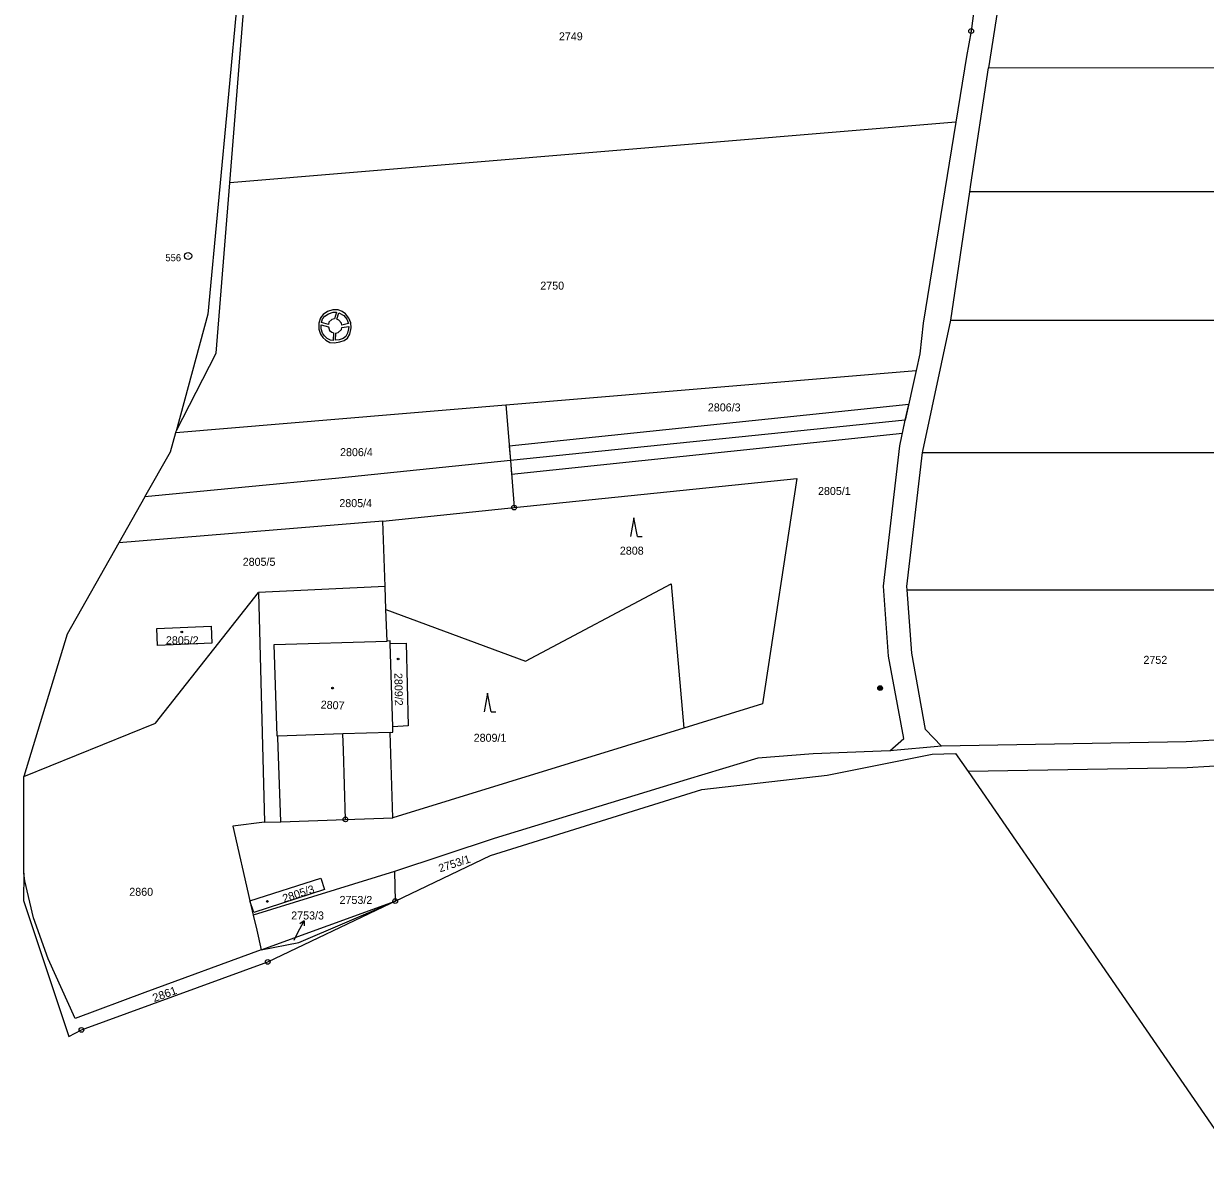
# Model space of a CAD drawing. Extents: x -606517 to -602431, y -1183120 to -1179397.
# Drawn here: x -605974 to -605722.9, y -1181182.9 to -1180939.5 of the extents above; entities that cross this region are included whole.
import ezdxf
from ezdxf.enums import TextEntityAlignment as Align

# ---------------------------------------------------------------- set-up
doc = ezdxf.new("R2010")
doc.units = 0
doc.header["$LTSCALE"] = 0.68
for name, color, linetype, lineweight in [('1', 7, 'Continuous', 25), ('13', 7, 'Continuous', 13), ('3', 7, 'Continuous', 25), ('4', 7, 'Continuous', 13), ('5', 7, 'Continuous', 25), ('6', 7, 'Continuous', 25), ('7', 7, 'Continuous', 13), ('8', 7, 'Continuous', 25)]:
    doc.layers.add(name, color=color, linetype=linetype, lineweight=lineweight)
doc.layers.add('2', color=7, linetype='Continuous')

msp = doc.modelspace()

# ---------------------------------------------------------------- linework, layer by layer
at = {"layer": '1'}
for p, q in [((-605769.1, -1180913.31), (-605772.66, -1180941.08)), ((-605765.31, -1180925.23), (-605769, -1180948.86)), ((-605927.95, -1180927.66), (-605930.47, -1180954.45)), ((-605930.21, -1180973.32), (-605927.2, -1180936.1)), ((-605772.66, -1180941.08), (-605773.62, -1180946.46)), ((-605773.62, -1180946.46), (-605775.89, -1180960.44)), ((-605769, -1180948.86), (-605635.12, -1180948.76)), ((-605772.7, -1180973.69), (-605769, -1180948.86)), ((-605930.47, -1180954.45), (-605934.87, -1181001.22)), ((-605775.89, -1180960.44), (-605930.21, -1180973.32)), ((-605775.89, -1180960.44), (-605782.83, -1181003.1)), ((-605933.13, -1181009.52), (-605930.21, -1180973.32)), ((-605772.93, -1180975.26), (-605772.7, -1180973.69)), ((-605776.96, -1181002.53), (-605772.93, -1180975.26)), ((-605599.33, -1180975.13), (-605772.93, -1180975.26)), ((-605934.87, -1181001.22), (-605941.63, -1181026.07)), ((-605782.83, -1181003.1), (-605783.59, -1181009.64)), ((-605782.95, -1181030.3), (-605776.96, -1181002.53)), ((-605776.96, -1181002.53), (-605609.37, -1181002.41)), ((-605941.63, -1181026.07), (-605933.13, -1181009.52)), ((-605783.59, -1181009.64), (-605784.37, -1181013.22)), ((-605871.52, -1181020.49), (-605784.37, -1181013.22)), ((-605784.37, -1181013.22), (-605786.65, -1181023.75)), ((-605941.7, -1181026.34), (-605871.52, -1181020.49)), ((-605871.52, -1181020.49), (-605870.57, -1181032.35)), ((-605786.65, -1181023.75), (-605870.57, -1181032.35)), ((-605787.84, -1181029.23), (-605786.65, -1181023.75)), ((-605942.83, -1181030.48), (-605941.7, -1181026.34)), ((-605941.7, -1181026.34), (-605941.63, -1181026.07)), ((-605948.25, -1181040.07), (-605942.83, -1181030.48)), ((-605791.32, -1181058.99), (-605787.84, -1181029.23)), ((-605786.3, -1181059.1), (-605782.99, -1181030.62)), ((-605782.99, -1181030.62), (-605782.95, -1181030.3)), ((-605782.99, -1181030.62), (-605619.15, -1181030.62)), ((-605870.57, -1181032.35), (-605907.03, -1181036.09)), ((-605870.57, -1181032.35), (-605869.78, -1181042.32)), ((-605907.03, -1181036.09), (-605948.25, -1181040.07)), ((-605869.78, -1181042.32), (-605809.71, -1181036.16)), ((-605809.71, -1181036.16), (-605816.98, -1181084.05)), ((-605948.25, -1181040.07), (-605953.76, -1181049.82)), ((-605897.65, -1181045.18), (-605869.78, -1181042.32)), ((-605897.65, -1181045.18), (-605953.76, -1181049.82)), ((-605897.18, -1181059.09), (-605897.65, -1181045.18)), ((-605897.18, -1181059.09), (-605924.12, -1181060.36)), ((-605897.01, -1181063.99), (-605897.18, -1181059.09)), ((-605867.39, -1181074.97), (-605836.4, -1181058.55)), ((-605836.4, -1181058.55), (-605833.7, -1181089.2)), ((-605790.24, -1181073.87), (-605791.32, -1181058.99)), ((-605786.25, -1181059.81), (-605786.3, -1181059.1)), ((-605945.99, -1181088.12), (-605924.12, -1181060.36)), ((-605924.12, -1181060.36), (-605922.84, -1181109.18)), ((-605786.25, -1181059.81), (-605631.54, -1181059.81)), ((-605785.27, -1181073.25), (-605786.25, -1181059.81)), ((-605897.01, -1181063.99), (-605867.39, -1181074.97)), ((-605896.79, -1181070.69), (-605897.01, -1181063.99)), ((-605895.57, -1181088.88), (-605896.09, -1181071.17)), ((-605786.94, -1181091.38), (-605790.24, -1181073.87)), ((-605782.35, -1181089.45), (-605785.27, -1181073.25)), ((-605816.98, -1181084.05), (-605833.7, -1181089.2)), ((-605639.05, -1181086.84), (-605726.94, -1181092.13)), ((-605973.98, -1181099.47), (-605945.99, -1181088.12)), ((-605789.97, -1181094.02), (-605786.94, -1181091.38)), ((-605778.98, -1181093.01), (-605782.35, -1181089.45)), ((-605789.97, -1181094.02), (-605806.25, -1181094.63)), ((-605778.98, -1181093.01), (-605789.97, -1181094.02)), ((-605726.94, -1181092.13), (-605778.98, -1181093.01)), ((-605656.78, -1181093.27), (-605726.73, -1181097.63)), ((-605817.98, -1181095.59), (-605833.03, -1181100.1)), ((-605806.25, -1181094.63), (-605817.98, -1181095.59)), ((-605775.96, -1181094.61), (-605773.33, -1181098.42)), ((-605829.9, -1181102.2), (-605803.29, -1181099.17)), ((-605726.73, -1181097.63), (-605773.33, -1181098.42)), ((-605773.33, -1181098.42), (-605715.07, -1181182.94)), ((-605974, -1181119.99), (-605973.98, -1181099.47)), ((-605833.03, -1181100.1), (-605874.01, -1181112.67)), ((-605874.79, -1181116.27), (-605829.9, -1181102.2)), ((-605922.84, -1181109.18), (-605929.52, -1181110.01)), ((-605922.84, -1181109.18), (-605919.34, -1181109.06)), ((-605919.34, -1181109.06), (-605905.62, -1181108.59)), ((-605905.62, -1181108.59), (-605895.53, -1181108.26)), ((-605929.52, -1181110.01), (-605925.93, -1181125.86)), ((-605874.01, -1181112.67), (-605895.17, -1181119.64)), ((-605895.05, -1181125.94), (-605874.79, -1181116.27)), ((-605973.78, -1181121.6), (-605974, -1181119.99)), ((-605971.92, -1181129.47), (-605973.78, -1181121.6)), ((-605895.17, -1181119.64), (-605925.23, -1181128.96)), ((-605895.17, -1181119.64), (-605895.05, -1181125.94)), ((-605925.93, -1181125.86), (-605925.23, -1181128.96)), ((-605923.5, -1181136.31), (-605895.05, -1181125.94)), ((-605922.14, -1181138.86), (-605895.96, -1181126.37)), ((-605915.5, -1181134.75), (-605895.96, -1181126.37)), ((-605895.96, -1181126.37), (-605895.05, -1181125.94)), ((-605968.83, -1181138.23), (-605971.92, -1181129.47)), ((-605925.23, -1181128.96), (-605924.47, -1181132.12)), ((-605924.47, -1181132.12), (-605923.5, -1181136.31)), ((-605923.5, -1181136.31), (-605948.22, -1181145.37)), ((-605923.5, -1181136.31), (-605915.5, -1181134.75)), ((-605963.04, -1181150.87), (-605968.83, -1181138.23)), ((-605961.73, -1181153.32), (-605922.14, -1181138.86)), ((-605948.22, -1181145.37), (-605963.04, -1181150.87)), ((-605964.42, -1181154.68), (-605961.73, -1181153.32))]:
    msp.add_line(p, q, dxfattribs=at)
for points in [[(-605953.76, -1181049.82), (-605964.73, -1181069.25), (-605973.98, -1181099.47)], [(-605896.09, -1181071.17), (-605896.1, -1181070.67), (-605896.79, -1181070.69)], [(-605896.09, -1181071.17), (-605892.69, -1181071.13), (-605892.32, -1181088.73), (-605895.57, -1181088.88)], [(-605896.14, -1181090.08), (-605895.54, -1181090.06), (-605895.57, -1181088.88)], [(-605833.7, -1181089.2), (-605895.53, -1181108.26), (-605896.14, -1181090.08)], [(-605803.29, -1181099.17), (-605780.96, -1181094.73), (-605775.96, -1181094.61)], [(-605974, -1181119.99), (-605974.01, -1181125.8), (-605964.42, -1181154.68)]]:
    msp.add_lwpolyline(points, dxfattribs=at)
for points in [[(-605945.53, -1181071.61), (-605945.7, -1181068.01), (-605934.14, -1181067.5), (-605933.99, -1181071.11)], [(-605925.93, -1181125.86), (-605910.87, -1181121.05), (-605910.07, -1181123.49), (-605925.06, -1181128.36)]]:
    msp.add_lwpolyline(points, close=True, dxfattribs=at)
at = {"layer": '13'}
for points in [[(-605908.32, -1181000.3), (-605909.44, -1181000.66), (-605910.34, -1181001.27), (-605910.94, -1181002), (-605911.25, -1181003.11), (-605911.26, -1181004.39), (-605910.96, -1181005.47), (-605910.45, -1181006.2), (-605909.79, -1181006.77), (-605908.94, -1181007.26), (-605907.97, -1181007.31), (-605906.84, -1181007.13), (-605905.9, -1181006.83), (-605905.18, -1181006.34), (-605904.69, -1181005.44), (-605904.42, -1181004.16), (-605904.49, -1181003.09), (-605904.9, -1181002.08), (-605905.62, -1181001.12), (-605906.32, -1181000.65), (-605907.16, -1181000.33)], [(-605907.55, -1181000.82), (-605907.98, -1181002.22), (-605908.53, -1181002.34), (-605909.17, -1181002.92), (-605909.26, -1181003.42), (-605910.69, -1181002.98), (-605910.48, -1181002.24), (-605910, -1181001.65), (-605909.22, -1181001.12), (-605908.24, -1181000.8)], [(-605905.96, -1181001.48), (-605905.34, -1181002.32), (-605904.99, -1181003.21), (-605906.39, -1181003.58), (-605906.48, -1181003.1), (-605907.01, -1181002.49), (-605907.48, -1181002.29), (-605907.05, -1181000.91)], [(-605909.26, -1181003.94), (-605909.02, -1181004.7), (-605908.53, -1181005.06), (-605908.18, -1181005.2), (-605908.22, -1181006.8), (-605908.8, -1181006.76), (-605909.49, -1181006.37), (-605910.07, -1181005.86), (-605910.5, -1181005.25), (-605910.76, -1181004.33), (-605910.75, -1181003.49)], [(-605904.94, -1181003.84), (-605904.97, -1181004.34), (-605905.17, -1181005.26), (-605905.56, -1181006), (-605906.12, -1181006.37), (-605906.96, -1181006.65), (-605907.72, -1181006.77), (-605907.68, -1181005.23), (-605907.17, -1181005.09), (-605906.46, -1181004.48), (-605906.4, -1181004.09)], [(-605787.25, -1181026.52), (-605786.65, -1181023.75), (-605785.94, -1181020.45), (-605870.82, -1181029.3), (-605870.57, -1181032.35), (-605870.34, -1181035.25)]]:
    msp.add_lwpolyline(points, close=True, dxfattribs=at)
at = {"layer": '3'}
for p, q in [((-605843.56, -1181048.5), (-605842.564, -1181048.5)), ((-605874.66, -1181085.72), (-605873.664, -1181085.72))]:
    msp.add_line(p, q, dxfattribs=at)
for points in [[(-605843.56, -1181048.5), (-605844.31, -1181044.5), (-605845.06, -1181048.5)], [(-605874.66, -1181085.72), (-605875.41, -1181081.72), (-605876.16, -1181085.72)]]:
    msp.add_lwpolyline(points, dxfattribs=at)
at = {"layer": '4'}
for p, q in [((-605906.17, -1181090.41), (-605919.97, -1181090.86)), ((-605896.14, -1181090.08), (-605906.17, -1181090.41))]:
    msp.add_line(p, q, dxfattribs=at)
for points in [[(-605919.97, -1181090.86), (-605920.15, -1181090.87), (-605920.79, -1181071.4), (-605896.79, -1181070.69)], [(-605919.34, -1181109.06), (-605919.96, -1181091.16), (-605919.97, -1181090.86)], [(-605905.62, -1181108.59), (-605906.07, -1181093.84), (-605906.17, -1181090.41)]]:
    msp.add_lwpolyline(points, dxfattribs=at)
at = {"layer": '5'}
for centre in [(-605940.3968, -1181068.7492), (-605894.4268, -1181074.4792), (-605908.3668, -1181080.6892), (-605922.2168, -1181126.0192)]:
    msp.add_circle(centre, 0.175, dxfattribs=at)
at = {"layer": '6'}
for radius in [0.5, 0.4, 0.3, 0.2, 0.1]:
    msp.add_circle((-605792.0134, -1181080.6799), radius, dxfattribs=at)
at = {"layer": '7'}
msp.add_line((-605914.418, -1181130.096), (-605915.318, -1181130.761), dxfattribs=at)
msp.add_lwpolyline([(-605916.54, -1181134.27), (-605915.78, -1181132.77), (-605914.418, -1181130.096), (-605914.426, -1181131.216)], dxfattribs=at)
at = {"layer": '8'}
for centre, radius in [((-605772.66, -1180941.0799), 0.5), ((-605772.66, -1180941.0799), 0.0303), ((-605939.05, -1180988.8598), 0.75), ((-605939.05, -1180988.8598), 0.03), ((-605869.78, -1181042.3199), 0.5), ((-605869.78, -1181042.3199), 0.0303), ((-605905.62, -1181108.5899), 0.5), ((-605905.62, -1181108.5899), 0.0303), ((-605895.05, -1181125.9399), 0.5), ((-605895.05, -1181125.9399), 0.0303), ((-605922.14, -1181138.8599), 0.5), ((-605922.14, -1181138.8599), 0.0303), ((-605961.73, -1181153.3199), 0.5), ((-605961.73, -1181153.3199), 0.0303)]:
    msp.add_circle(centre, radius, dxfattribs=at)

# ---------------------------------------------------------------- texts
at = {"layer": '2'}
for s, p in [('2749', (-605860.26, -1180943.035)), ('2750', (-605864.22, -1180996.015)), ('2806/3', (-605828.61, -1181021.885)), ('2806/4', (-605906.77, -1181031.395)), ('2808', (-605847.31, -1181052.325)), ('2752', (-605736.05, -1181075.525)), ('2860', (-605951.56, -1181124.815))]:
    msp.add_text(s, height=1.7, dxfattribs=at).set_placement(p)
for s, p in [('2805/1', (-605801.73, -1181039.645)), ('2805/4', (-605903.45, -1181042.225)), ('2805/5', (-605923.98, -1181054.695)), ('2805/2', (-605940.3, -1181071.365)), ('2809/1', (-605874.9, -1181092.085)), ('2753/2', (-605903.4, -1181126.542)), ('2753/3', (-605913.67, -1181129.845))]:
    msp.add_text(s, height=1.7, dxfattribs=at).set_placement(p, align=Align.CENTER)
for s, rotation, p in [('2809/2', 271, (-605895.1744, -1181080.9542)), ('2807', 357, (-605908.3895, -1181085.1351)), ('2753/1', 18, (-605882.2197, -1181118.7664)), ('2805/3', 18, (-605915.3647, -1181125.1704))]:
    msp.add_text(s, height=1.7, rotation=rotation, dxfattribs=at).set_placement(p, align=Align.CENTER)
at = {"layer": '2', "width": 1.05}
msp.add_text('2861', height=1.7, rotation=20, dxfattribs=at).set_placement((-605946.264, -1181147.399))
at = {"layer": '8'}
msp.add_text('556', height=1.5, dxfattribs=at).set_placement((-605940.549, -1180989.977), align=Align.RIGHT)

doc.saveas('drawing.dxf')
